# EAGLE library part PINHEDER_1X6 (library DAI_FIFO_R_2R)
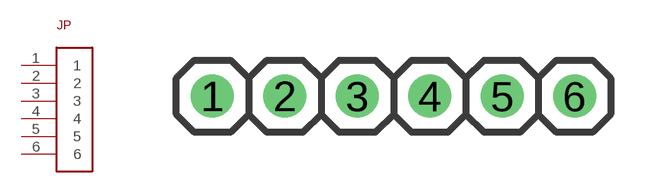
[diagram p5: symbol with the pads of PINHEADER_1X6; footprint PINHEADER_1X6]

Designator prefix JP

## PINHEDER_1X6  [PINHEADER_1X6]
1  1  pas
2  2  pas
3  3  pas
4  4  pas
5  5  pas
6  6  pas

## Footprint PINHEADER_1X6 (pad centres in mm)
drill 1 round: 1 -7.62,0; 2 -5.08,0; 3 -2.54,0; 4 0,0; 5 2.54,0; 6 5.08,0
